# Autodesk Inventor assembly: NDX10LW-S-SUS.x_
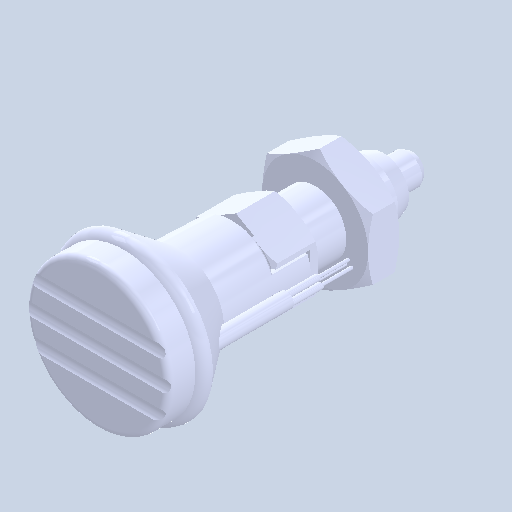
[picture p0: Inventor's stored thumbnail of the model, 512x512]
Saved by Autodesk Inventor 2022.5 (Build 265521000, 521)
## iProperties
Created: 2024-05
Part Number: NDX10LW-S-SUS.x_
Document SubType Name: Assembly
Designer: ImaoCorp
Author: ImaoCorp
Sending System: SOLIDWORKS 2022-2022290
MC: AMD64
MC_MODEL: Intel64 Family 6 Model 60 Stepping 3, GenuineIntel
OS: Windows_NT
FRU: Parasolid Version 33.1, build 260,  4-25-2022
FORMAT: text
GUISE: transmit
KEY: FILENDX10LW-S-SUS.x_t
DATE: Tue May 21 08:48:05 2024
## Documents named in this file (3)
- X:\14_SW2022-Inv2022\保留中\kipp\KME_データ\n\ndx10lw-s-sus\NDX10LW-S-SUS.x_.iam
- X:\14_SW2022-Inv2022\保留中\kipp\KME_データ\n\ndx10lw-s-sus\NDX10LW-S-SUS_01.ipt
- X:\14_SW2022-Inv2022\保留中\kipp\KME_データ\n\ndx10lw-s-sus\NDX10LW-S-SUS_02.ipt
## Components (2 placed, 2 different names)
1. NDX10LW-S-SUS_01
2. NDX10LW-S-SUS_02
